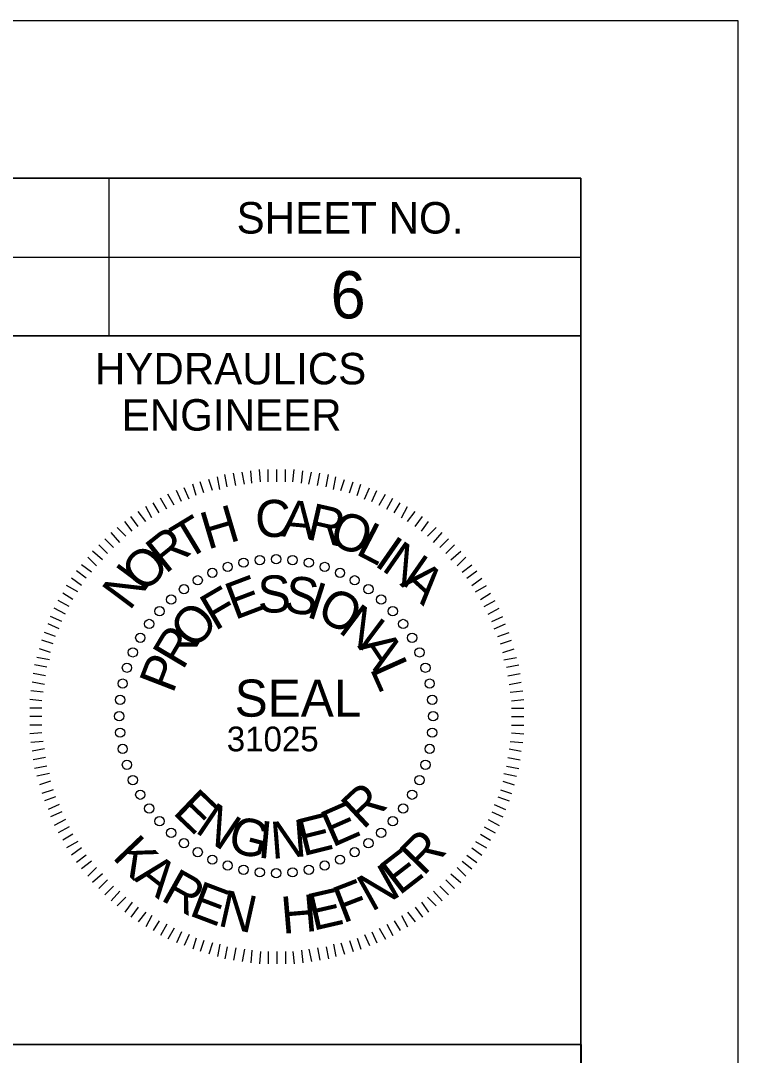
# Model space of a CAD drawing. Extents: x 573058.4 to 573116.8, y -55221.3 to -55199.3.
# Drawn here: x 573109.734 to 573112.014, y -55202.584 to -55199.298 of the extents above; entities that cross this region are included whole.
import ezdxf

# ---------------------------------------------------------------- set-up
doc = ezdxf.new("R2010")
doc.units = 0
for name, color, linetype in [('Old_Level_5', 7, 'Continuous'), ('Scratch_Level_1', 7, 'Continuous'), ('Sheet Data Field CELL', 7, 'Continuous'), ('Sheet Plot Border Inside CELL', 7, 'Continuous'), ('Sheet Profile CELL', 7, 'Continuous'), ('Sheet Sticker Exception Certification CELL', 7, 'Continuous')]:
    doc.layers.add(name, color=color, linetype=linetype)

msp = doc.modelspace()

# ---------------------------------------------------------------- linework, layer by layer
at = {"layer": 'Old_Level_5'}
for p, q in [((573110.4691, -55200.7668), (573110.4654, -55200.7275)), ((573110.4966, -55200.7631), (573110.4929, -55200.7237)), ((573110.5204, -55200.7631), (573110.5204, -55200.7237)), ((573110.5479, -55200.7631), (573110.5479, -55200.7237)), ((573110.5479, -55200.7631), (573110.5479, -55200.7237)), ((573110.5479, -55200.7631), (573110.5479, -55200.7237)), ((573110.5479, -55200.7631), (573110.5479, -55200.7237)), ((573110.5479, -55200.7631), (573110.5479, -55200.7237)), ((573110.5479, -55200.7631), (573110.5479, -55200.7237)), ((573110.5479, -55200.7631), (573110.5479, -55200.7237)), ((573110.5479, -55200.7631), (573110.5479, -55200.7237)), ((573110.5479, -55200.7631), (573110.5479, -55200.7237)), ((573110.5479, -55200.7631), (573110.5479, -55200.7237)), ((573110.5479, -55200.7631), (573110.5479, -55200.7237)), ((573110.5479, -55200.7631), (573110.5479, -55200.7237)), ((573110.5479, -55200.7631), (573110.5479, -55200.7237)), ((573110.5479, -55200.7631), (573110.5479, -55200.7237)), ((573110.5479, -55200.7631), (573110.5479, -55200.7237)), ((573110.5479, -55200.7631), (573110.5479, -55200.7237)), ((573110.5479, -55200.7631), (573110.5479, -55200.7237)), ((573110.5479, -55200.7631), (573110.5479, -55200.7237)), ((573110.5479, -55200.7631), (573110.5479, -55200.7237)), ((573110.5479, -55200.7631), (573110.5479, -55200.7237)), ((573110.5479, -55200.7631), (573110.5479, -55200.7237)), ((573110.5479, -55200.7631), (573110.5479, -55200.7237)), ((573110.5479, -55200.7631), (573110.5479, -55200.7237)), ((573110.5479, -55200.7631), (573110.5479, -55200.7237)), ((573110.5479, -55200.7631), (573110.5479, -55200.7237)), ((573110.5479, -55200.7631), (573110.5479, -55200.7237)), ((573110.5479, -55200.7631), (573110.5479, -55200.7237)), ((573110.5479, -55200.7631), (573110.5479, -55200.7237)), ((573110.5479, -55200.7631), (573110.5479, -55200.7237)), ((573110.5479, -55200.7631), (573110.5479, -55200.7237)), ((573110.5754, -55200.7631), (573110.5754, -55200.7237)), ((573110.5985, -55200.7631), (573110.6029, -55200.7237)), ((573110.626, -55200.7668), (573110.6304, -55200.7275)), ((573110.316, -55200.7981), (573110.3041, -55200.7631)), ((573110.3435, -55200.7906), (573110.3316, -55200.755)), ((573110.3672, -55200.7868), (573110.3591, -55200.7475)), ((573110.3904, -55200.7787), (573110.3829, -55200.7393)), ((573110.4179, -55200.775), (573110.4104, -55200.7356)), ((573110.4454, -55200.7706), (573110.4379, -55200.7318)), ((573110.6497, -55200.7706), (573110.6579, -55200.7318)), ((573110.6772, -55200.775), (573110.6847, -55200.7356)), ((573110.7047, -55200.7787), (573110.7122, -55200.7393)), ((573110.7285, -55200.7868), (573110.736, -55200.7475)), ((573110.7516, -55200.7906), (573110.7635, -55200.755)), ((573110.7791, -55200.7981), (573110.791, -55200.7631)), ((573110.2454, -55200.8256), (573110.2297, -55200.7906)), ((573110.2691, -55200.8181), (573110.2535, -55200.7825)), ((573110.2922, -55200.8062), (573110.281, -55200.7706)), ((573110.8029, -55200.8062), (573110.8147, -55200.7706)), ((573110.8266, -55200.8181), (573110.8422, -55200.7825)), ((573110.8497, -55200.8256), (573110.8654, -55200.7906)), ((573110.1985, -55200.8493), (573110.1785, -55200.8143)), ((573110.2216, -55200.8375), (573110.2022, -55200.8025)), ((573110.8735, -55200.8375), (573110.8929, -55200.8025)), ((573110.8972, -55200.8493), (573110.9166, -55200.8143)), ((573110.1316, -55200.8887), (573110.1079, -55200.8575)), ((573110.151, -55200.8768), (573110.1316, -55200.8412)), ((573110.1747, -55200.8612), (573110.1554, -55200.83)), ((573110.9204, -55200.8612), (573110.9404, -55200.83)), ((573110.9441, -55200.8768), (573110.9635, -55200.8412)), ((573110.9635, -55200.8887), (573110.9872, -55200.8575)), ((573110.0885, -55200.92), (573110.0647, -55200.8887)), ((573110.1079, -55200.9043), (573110.0847, -55200.8731)), ((573110.9872, -55200.9043), (573111.011, -55200.8731)), ((573111.0072, -55200.92), (573111.0304, -55200.8887)), ((573110.0491, -55200.9556), (573110.0216, -55200.9237)), ((573110.0685, -55200.9356), (573110.041, -55200.9081)), ((573111.0266, -55200.9356), (573111.0541, -55200.9081)), ((573111.046, -55200.9556), (573111.0735, -55200.9237)), ((573110.0297, -55200.9712), (573110.0022, -55200.9437)), ((573111.066, -55200.9712), (573111.0935, -55200.9437)), ((573109.9941, -55201.0106), (573109.9629, -55200.9831)), ((573110.0097, -55200.9906), (573109.9822, -55200.9631)), ((573111.0854, -55200.9906), (573111.1129, -55200.9631)), ((573111.101, -55201.0106), (573111.1329, -55200.9831)), ((573109.9591, -55201.0493), (573109.9272, -55201.0262)), ((573109.9747, -55201.03), (573109.9472, -55201.0025)), ((573111.121, -55201.03), (573111.1485, -55201.0025)), ((573111.1366, -55201.0493), (573111.1679, -55201.0262)), ((573109.9429, -55201.0693), (573109.9116, -55201.0456)), ((573111.1522, -55201.0693), (573111.1835, -55201.0456)), ((573109.9272, -55201.0925), (573109.896, -55201.0693)), ((573111.1679, -55201.0925), (573111.1991, -55201.0693)), ((573109.8997, -55201.1362), (573109.8685, -55201.1162)), ((573109.9154, -55201.1125), (573109.8804, -55201.0925)), ((573111.1797, -55201.1125), (573111.2147, -55201.0925)), ((573111.1954, -55201.1362), (573111.2266, -55201.1162)), ((573109.8879, -55201.1593), (573109.8529, -55201.14)), ((573111.2072, -55201.1593), (573111.2422, -55201.14)), ((573109.8647, -55201.2068), (573109.8291, -55201.1906)), ((573109.8766, -55201.1831), (573109.841, -55201.1637)), ((573111.2191, -55201.1831), (573111.2541, -55201.1637)), ((573111.231, -55201.2068), (573111.266, -55201.1906)), ((573109.8566, -55201.23), (573109.8216, -55201.2143)), ((573111.2385, -55201.23), (573111.2741, -55201.2143)), ((573109.8447, -55201.2537), (573109.8097, -55201.2418)), ((573111.2504, -55201.2537), (573111.286, -55201.2418)), ((573109.8372, -55201.2775), (573109.8016, -55201.2656)), ((573111.2585, -55201.2775), (573111.2935, -55201.2656)), ((573109.8254, -55201.3281), (573109.786, -55201.3206)), ((573109.8291, -55201.305), (573109.7941, -55201.2931)), ((573111.266, -55201.305), (573111.3016, -55201.2931)), ((573111.2697, -55201.3281), (573111.3091, -55201.3206)), ((573109.8172, -55201.3518), (573109.7785, -55201.3437)), ((573111.2779, -55201.3518), (573111.3172, -55201.3437)), ((573109.8135, -55201.3793), (573109.7741, -55201.3712)), ((573111.2816, -55201.3793), (573111.321, -55201.3712)), ((573109.8097, -55201.4068), (573109.7704, -55201.3987)), ((573111.286, -55201.4068), (573111.3247, -55201.3987)), ((573109.8016, -55201.4581), (573109.7629, -55201.4537)), ((573109.806, -55201.4306), (573109.7666, -55201.4262)), ((573111.2897, -55201.4306), (573111.3291, -55201.4262)), ((573111.2935, -55201.4581), (573111.3329, -55201.4537)), ((573109.8016, -55201.4812), (573109.7629, -55201.4812)), ((573111.2935, -55201.4812), (573111.3329, -55201.4812)), ((573109.8016, -55201.5087), (573109.7629, -55201.5087)), ((573111.2935, -55201.5087), (573111.3329, -55201.5087)), ((573109.8016, -55201.5362), (573109.7629, -55201.5362)), ((573111.2935, -55201.5362), (573111.3329, -55201.5362)), ((573109.8016, -55201.56), (573109.7629, -55201.5637)), ((573111.2935, -55201.56), (573111.3329, -55201.5637)), ((573109.806, -55201.5875), (573109.7666, -55201.5912)), ((573109.8097, -55201.6106), (573109.7704, -55201.6187)), ((573111.286, -55201.6106), (573111.3247, -55201.6187)), ((573111.2897, -55201.5875), (573111.3291, -55201.5912)), ((573109.8135, -55201.6381), (573109.7741, -55201.6462)), ((573111.2816, -55201.6381), (573111.321, -55201.6462)), ((573109.8172, -55201.6656), (573109.7785, -55201.6737)), ((573111.2779, -55201.6656), (573111.3172, -55201.6737)), ((573109.8254, -55201.6893), (573109.786, -55201.6975)), ((573109.8291, -55201.7131), (573109.7941, -55201.725)), ((573111.266, -55201.7131), (573111.3016, -55201.725)), ((573111.2697, -55201.6893), (573111.3091, -55201.6975)), ((573109.8372, -55201.7406), (573109.8016, -55201.7525)), ((573111.2585, -55201.7406), (573111.2935, -55201.7525)), ((573109.8447, -55201.7637), (573109.8097, -55201.7756)), ((573111.2504, -55201.7637), (573111.286, -55201.7756)), ((573109.8566, -55201.7875), (573109.8216, -55201.8031)), ((573109.8647, -55201.8112), (573109.8291, -55201.8268)), ((573111.231, -55201.8112), (573111.266, -55201.8268)), ((573111.2385, -55201.7875), (573111.2741, -55201.8031)), ((573109.8766, -55201.835), (573109.841, -55201.8543)), ((573111.2191, -55201.835), (573111.2541, -55201.8543)), ((573109.8879, -55201.8581), (573109.8529, -55201.8781)), ((573111.2072, -55201.8581), (573111.2422, -55201.8781)), ((573109.8997, -55201.8818), (573109.8685, -55201.9012)), ((573109.9154, -55201.9056), (573109.8804, -55201.925)), ((573111.1797, -55201.9056), (573111.2147, -55201.925)), ((573111.1954, -55201.8818), (573111.2266, -55201.9012)), ((573109.9272, -55201.925), (573109.896, -55201.9487)), ((573111.1679, -55201.925), (573111.1991, -55201.9487)), ((573109.9429, -55201.9487), (573109.9116, -55201.9718)), ((573109.9591, -55201.9681), (573109.9272, -55201.9918)), ((573111.1366, -55201.9681), (573111.1679, -55201.9918)), ((573111.1522, -55201.9487), (573111.1835, -55201.9718)), ((573109.9747, -55201.9881), (573109.9472, -55202.015)), ((573109.9941, -55202.0075), (573109.9629, -55202.035)), ((573111.101, -55202.0075), (573111.1329, -55202.035)), ((573111.121, -55201.9881), (573111.1485, -55202.015)), ((573110.0097, -55202.0268), (573109.9822, -55202.0543)), ((573111.0854, -55202.0268), (573111.1129, -55202.0543)), ((573110.0297, -55202.0468), (573110.0022, -55202.0743)), ((573110.0491, -55202.0625), (573110.0216, -55202.0937)), ((573111.046, -55202.0625), (573111.0735, -55202.0937)), ((573111.066, -55202.0468), (573111.0935, -55202.0743)), ((573110.0685, -55202.0818), (573110.041, -55202.1093)), ((573110.0885, -55202.0975), (573110.0647, -55202.1293)), ((573111.0072, -55202.0975), (573111.0304, -55202.1293)), ((573111.0266, -55202.0818), (573111.0541, -55202.1093)), ((573110.1079, -55202.1137), (573110.0847, -55202.145)), ((573110.1316, -55202.1293), (573110.1079, -55202.1606)), ((573110.151, -55202.1406), (573110.1316, -55202.1762)), ((573110.9441, -55202.1406), (573110.9635, -55202.1762)), ((573110.9635, -55202.1293), (573110.9872, -55202.1606)), ((573110.9872, -55202.1137), (573111.011, -55202.145)), ((573110.1747, -55202.1568), (573110.1554, -55202.1881)), ((573110.1985, -55202.1681), (573110.1785, -55202.2037)), ((573110.8972, -55202.1681), (573110.9166, -55202.2037)), ((573110.9204, -55202.1568), (573110.9404, -55202.1881)), ((573110.2216, -55202.18), (573110.2022, -55202.2156)), ((573110.2454, -55202.1918), (573110.2297, -55202.2275)), ((573110.2691, -55202.2), (573110.2535, -55202.235)), ((573110.8266, -55202.2), (573110.8422, -55202.235)), ((573110.8497, -55202.1918), (573110.8654, -55202.2275)), ((573110.8735, -55202.18), (573110.8929, -55202.2156)), ((573110.2922, -55202.2118), (573110.281, -55202.2468)), ((573110.316, -55202.2193), (573110.3041, -55202.255)), ((573110.3435, -55202.2275), (573110.3316, -55202.2625)), ((573110.3672, -55202.2312), (573110.3591, -55202.2706)), ((573110.3904, -55202.2393), (573110.3829, -55202.2781)), ((573110.7047, -55202.2393), (573110.7122, -55202.2781)), ((573110.7285, -55202.2312), (573110.736, -55202.2706)), ((573110.7516, -55202.2275), (573110.7635, -55202.2625)), ((573110.7791, -55202.2193), (573110.791, -55202.255)), ((573110.8029, -55202.2118), (573110.8147, -55202.2468)), ((573110.4179, -55202.2431), (573110.4104, -55202.2825)), ((573110.4454, -55202.2468), (573110.4379, -55202.2862)), ((573110.4691, -55202.2506), (573110.4654, -55202.29)), ((573110.4966, -55202.255), (573110.4929, -55202.2937)), ((573110.5204, -55202.255), (573110.5204, -55202.2937)), ((573110.5479, -55202.255), (573110.5479, -55202.2937)), ((573110.5754, -55202.255), (573110.5754, -55202.2937)), ((573110.5985, -55202.255), (573110.6029, -55202.2937)), ((573110.626, -55202.2506), (573110.6304, -55202.29)), ((573110.6497, -55202.2468), (573110.6579, -55202.2862)), ((573110.6772, -55202.2431), (573110.6847, -55202.2825))]:
    msp.add_line(p, q, dxfattribs=at)
for centre in [(573110.392, -55201.0332), (573110.392, -55201.0332), (573110.4424, -55201.0197), (573110.4424, -55201.0197), (573110.4939, -55201.0115), (573110.4939, -55201.0115), (573110.546, -55201.0088), (573110.546, -55201.0088), (573110.5981, -55201.0115), (573110.6497, -55201.0197), (573110.7001, -55201.0332), (573110.3432, -55201.0519), (573110.3432, -55201.0519), (573110.7488, -55201.0519), (573110.253, -55201.104), (573110.253, -55201.104), (573110.2968, -55201.0756), (573110.2968, -55201.0756), (573110.7953, -55201.0756), (573110.8391, -55201.104), (573110.2124, -55201.1369), (573110.2124, -55201.1369), (573110.8796, -55201.1369), (573110.1755, -55201.1738), (573110.1755, -55201.1738), (573110.9165, -55201.1738), (573110.1427, -55201.2143), (573110.1427, -55201.2143), (573110.9494, -55201.2143), (573110.1143, -55201.2581), (573110.1143, -55201.2581), (573110.9778, -55201.2581), (573110.0906, -55201.3046), (573110.0906, -55201.3046), (573111.0015, -55201.3046), (573110.0719, -55201.3533), (573110.0719, -55201.3533), (573111.0202, -55201.3533), (573110.0584, -55201.4037), (573110.0584, -55201.4037), (573111.0337, -55201.4037), (573110.0502, -55201.4552), (573110.0502, -55201.4552), (573111.0418, -55201.4552), (573110.0475, -55201.5073), (573110.0475, -55201.5073), (573111.0446, -55201.5073), (573110.0502, -55201.5595), (573110.0502, -55201.5595), (573111.0418, -55201.5595), (573110.0584, -55201.611), (573110.0584, -55201.611), (573111.0337, -55201.611), (573110.0719, -55201.6614), (573110.0719, -55201.6614), (573111.0202, -55201.6614), (573110.0906, -55201.7101), (573110.0906, -55201.7101), (573111.0015, -55201.7101), (573110.1143, -55201.7566), (573110.1143, -55201.7566), (573110.9778, -55201.7566), (573110.1427, -55201.8004), (573110.1427, -55201.8004), (573110.9494, -55201.8004), (573110.1755, -55201.8409), (573110.1755, -55201.8409), (573110.9165, -55201.8409), (573110.2124, -55201.8778), (573110.2124, -55201.8778), (573110.8796, -55201.8778), (573110.253, -55201.9107), (573110.253, -55201.9107), (573110.8391, -55201.9107), (573110.2968, -55201.9391), (573110.2968, -55201.9391), (573110.7953, -55201.9391), (573110.3432, -55201.9628), (573110.3432, -55201.9628), (573110.392, -55201.9815), (573110.392, -55201.9815), (573110.7001, -55201.9815), (573110.7488, -55201.9628), (573110.4424, -55201.995), (573110.4424, -55201.995), (573110.4939, -55202.0032), (573110.4939, -55202.0032), (573110.546, -55202.0059), (573110.5981, -55202.0032), (573110.6497, -55201.995)]:
    msp.add_circle(centre, 0.0147, dxfattribs=at)
at = {"layer": 'Scratch_Level_1'}
msp.add_line((573110.547, -55201.5087), (573110.547, -55201.5087), dxfattribs=at)
at = {"layer": 'Sheet Plot Border Inside CELL'}
msp.add_lwpolyline([(573112.0142, -55199.2984), (573078.0142, -55199.2984), (573078.0142, -55221.2984), (573112.0142, -55221.2984)], close=True, dxfattribs=at)
at = {"layer": 'Sheet Profile CELL'}
for p, q in [((573110.0142, -55199.7994), (573110.0142, -55200.2994)), ((573107.5142, -55200.0494), (573111.5142, -55200.0494))]:
    msp.add_line(p, q, dxfattribs=at)
for points in [[(573111.5142, -55199.7984), (573081.5142, -55199.7984), (573081.5142, -55220.7984), (573111.5142, -55220.7984)], [(573107.5142, -55199.7984), (573111.5142, -55199.7984), (573111.5142, -55200.2994), (573107.5142, -55200.2994)], [(573109.5142, -55200.2994), (573111.5142, -55200.2994), (573111.5142, -55202.5494), (573109.5142, -55202.5494)]]:
    msp.add_lwpolyline(points, close=True, dxfattribs=at)
at = {"layer": 'Sheet Sticker Exception Certification CELL'}
for p, q in [((573107.5142, -55202.5494), (573111.5149, -55202.5494)), ((573111.5149, -55202.5494), (573111.5149, -55203.0194))]:
    msp.add_line(p, q, dxfattribs=at)

# ---------------------------------------------------------------- texts
at = {"layer": 'Old_Level_5'}
for s, height, rotation, p in [('C', 0.1178, 1.8409, (573110.481, -55200.94)), ('A', 0.1178, 354.4936, (573110.5591, -55200.9356)), ('H', 0.1178, 16.5355, (573110.3279, -55200.9787)), ('R', 0.1173, 347.1464, (573110.6379, -55200.9437)), ('O', 0.1178, 339.7991, (573110.7085, -55200.9593)), ('T', 0.1178, 31.23, (573110.261, -55201.0143)), ('L', 0.1173, 332.4518, (573110.7947, -55200.9906)), ('R', 0.1178, 38.5773, (573110.1941, -55201.0575)), ('I', 0.1178, 325.1046, (573110.8541, -55201.0262)), ('N', 0.1178, 325.1046, (573110.8772, -55201.0418)), ('O', 0.1178, 45.9246, (573110.1279, -55201.12)), ('N', 0.1178, 53.2718, (573110.0804, -55201.175)), ('E', 0.1178, 20.7502, (573110.4141, -55201.2025)), ('S', 0.1178, 1.4893, (573110.4885, -55201.1793)), ('A', 0.1178, 317.7573, (573110.9366, -55201.0887)), ('F', 0.1173, 30.3806, (573110.3516, -55201.2381)), ('S', 0.1178, 351.8588, (573110.5672, -55201.175)), ('I', 0.1178, 342.2284, (573110.6379, -55201.1906)), ('O', 0.1178, 332.5979, (573110.6691, -55201.195)), ('O', 0.1178, 49.6415, (573110.2885, -55201.3006)), ('N', 0.1178, 322.9675, (573110.7397, -55201.2381)), ('R', 0.1178, 59.272, (573110.2491, -55201.3637)), ('A', 0.1178, 303.7066, (573110.8029, -55201.285)), ('P', 0.1178, 68.9024, (573110.2179, -55201.4381)), ('L', 0.1178, 294.0761, (573110.8422, -55201.3556)), ('E', 0.1178, 316.3156, (573110.2141, -55201.815)), ('R', 0.1178, 42.9896, (573110.8222, -55201.87)), ('E', 0.1173, 23.7287, (573110.7241, -55201.925)), ('N', 0.1178, 325.946, (573110.2847, -55201.8737)), ('E', 0.1178, 14.0983, (573110.6304, -55201.9525)), ('G', 0.1178, 345.2069, (573110.3866, -55201.9331)), ('I', 0.1178, 354.8374, (573110.4847, -55201.9562)), ('N', 0.1173, 4.4678, (573110.5322, -55201.9606)), ('R', 0.1175, 45.7969, (573111.0136, -55202.018)), ('K', 0.1175, 313.7767, (573110.0225, -55201.9562)), ('E', 0.1175, 37.6963, (573110.9371, -55202.0785)), ('A', 0.1175, 321.8774, (573110.0908, -55202.0257)), ('N', 0.1175, 29.1693, (573110.8484, -55202.1299)), ('R', 0.1175, 330.6886, (573110.1754, -55202.0896)), ('E', 0.1175, 339.2155, (573110.2656, -55202.1385)), ('F', 0.1175, 21.0687, (573110.7578, -55202.1661)), ('N', 0.1175, 347.3161, (573110.3572, -55202.1719)), ('H', 0.1175, 4.8675, (573110.5661, -55202.1986)), ('E', 0.1175, 12.9681, (573110.6631, -55202.1891))]:
    msp.add_text(s, height=height, rotation=rotation, dxfattribs=at).set_placement(p)
for s, height, p in [('SEAL', 0.11777, (573110.4141, -55201.5087)), ('31025', 0.0785, (573110.3891, -55201.6187))]:
    msp.add_text(s, height=height, dxfattribs=at).set_placement(p)
at = {"layer": 'Sheet Data Field CELL'}
msp.add_text('6', height=0.15, dxfattribs=at).set_placement((573110.7188, -55200.2439))
at = {"layer": 'Sheet Profile CELL'}
for s, p in [('SHEET NO.', (573110.4202, -55199.9744)), ('HYDRAULICS', (573109.9702, -55200.4534)), ('ENGINEER', (573110.0552, -55200.6004))]:
    msp.add_text(s, height=0.1, dxfattribs=at).set_placement(p)

doc.saveas('drawing.dxf')
